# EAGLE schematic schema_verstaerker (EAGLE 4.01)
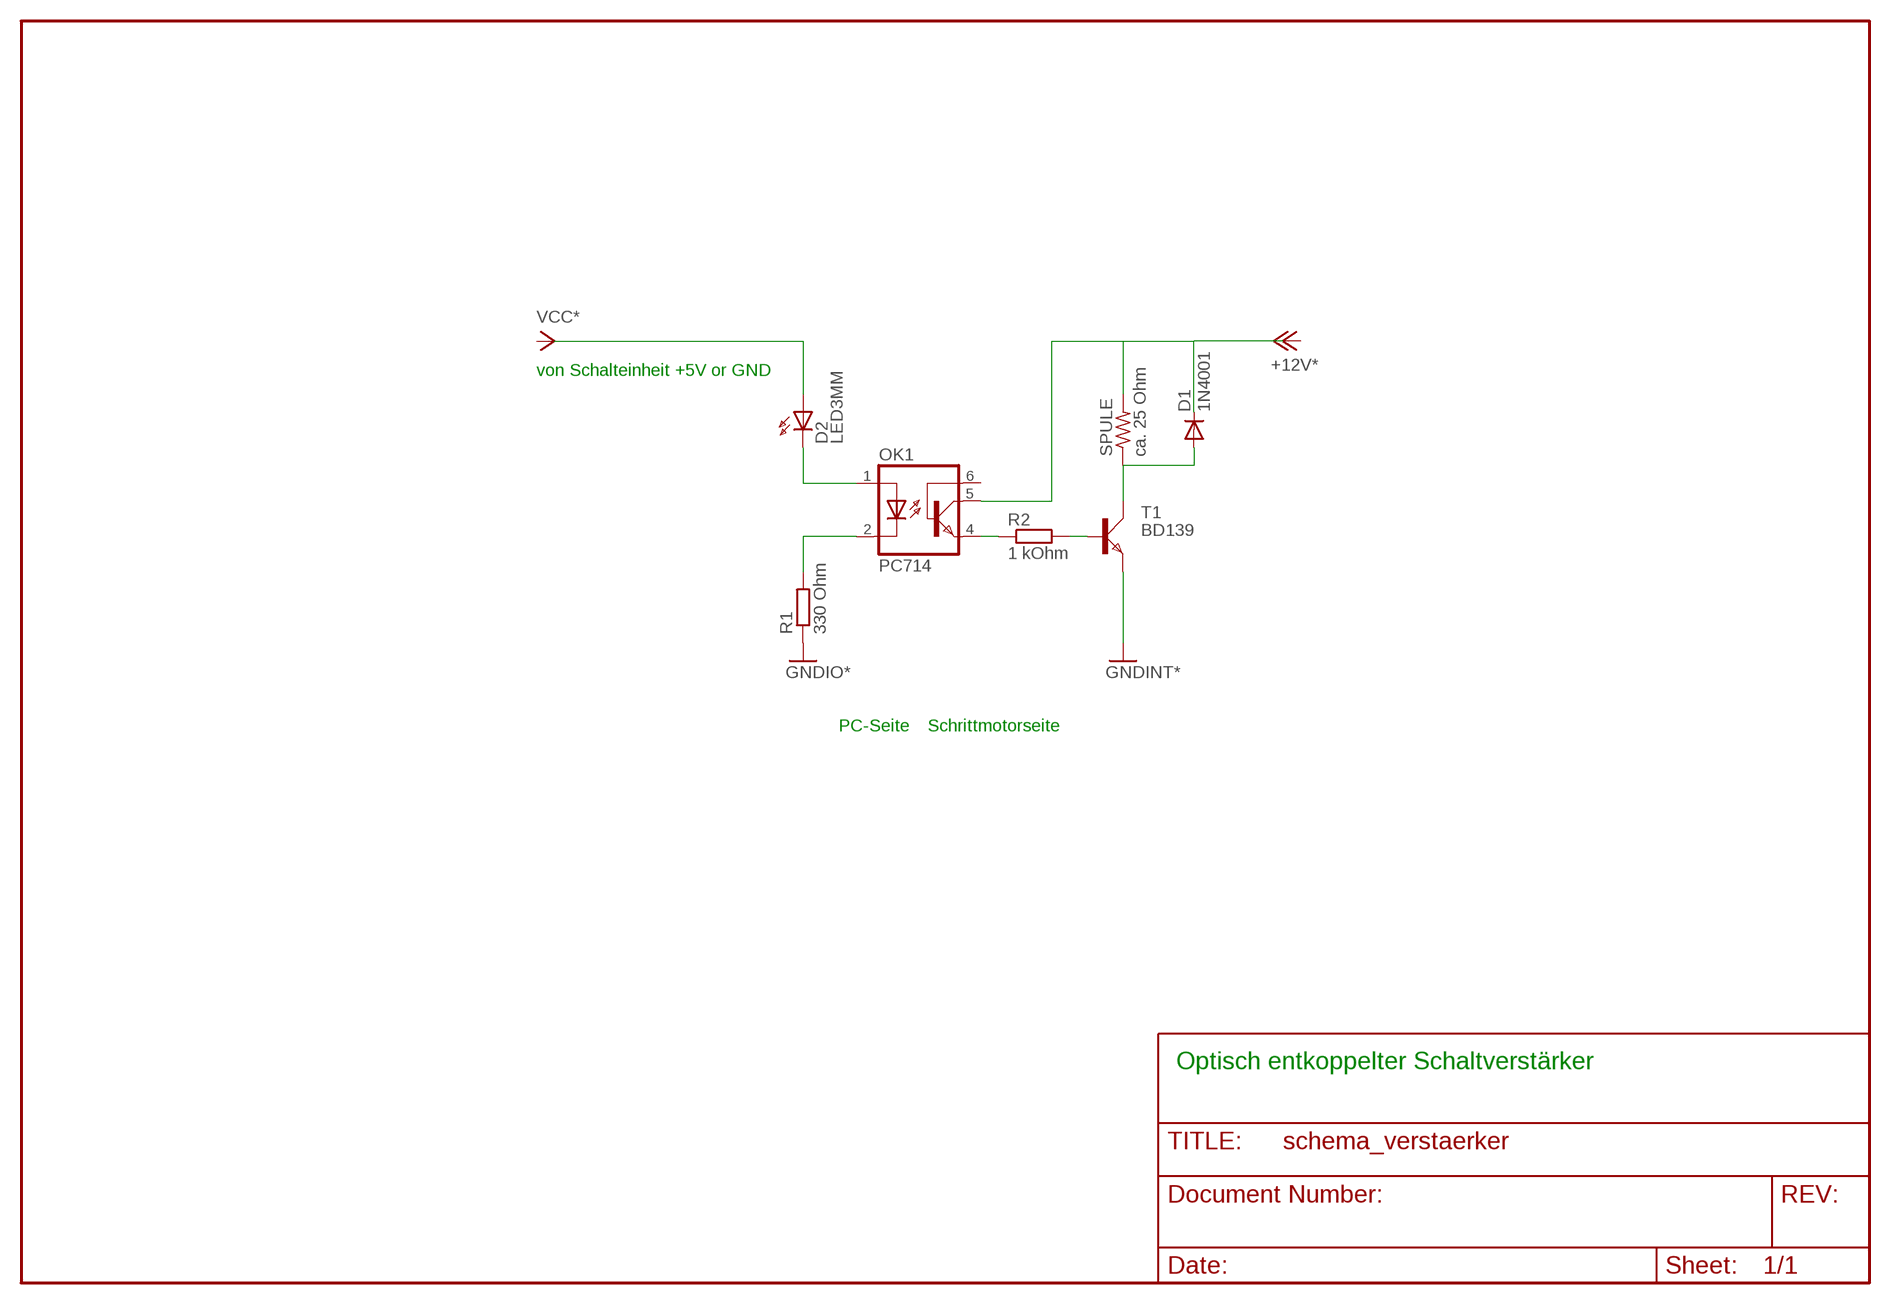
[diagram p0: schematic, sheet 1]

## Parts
D1  1N4001  1N4004  [DO41-10]
D2  LED3MM  [LED3MM]
OK1  PC714  PC110  [DIL06]
R1  330 Ohm  R-EU_0204/5  [0204/5]
R2  1 kOhm  R-EU_0204/5  [0204/5]
SPULE  ca. 25 Ohm  R-US_0204/7  [0204/7]
T1  BD139  [TO126AV]

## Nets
GNDINT: T1.E ; supply symbol labelled GNDINT*
GNDIO: R1.1 ; supply symbol labelled GNDIO*
N$1: OK1.4(EMI) R2.1
N$2: R2.2 T1.B
N$3: D1.A SPULE.1 T1.C
N$4: D2.A
N$5: D2.K(C) OK1.1(A)
N$6: OK1.2(C) R1.2
N$7: D1.K(C) OK1.5(COL) SPULE.2
Unconnected: OK1.6(BAS)

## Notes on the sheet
- von Schalteinheit +5V or GND
- PC-Seite | Schrittmotorseite
- Optisch entkoppelter Schaltverstärker

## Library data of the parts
D1 = diode:1N4004: DIODE
D2 = led:LED3MM: LED
OK1 = optocoupler:PC110: SHARP OPTO COUPLER
R1 R2 = rcl:R-EU_: RESISTOR, European symbol
SPULE = rcl:R-US_: RESISTOR, American symbol
T1 = transistor-power:BD139: NPN TRANSISTOR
